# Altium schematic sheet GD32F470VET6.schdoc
size 127 x 101 mm
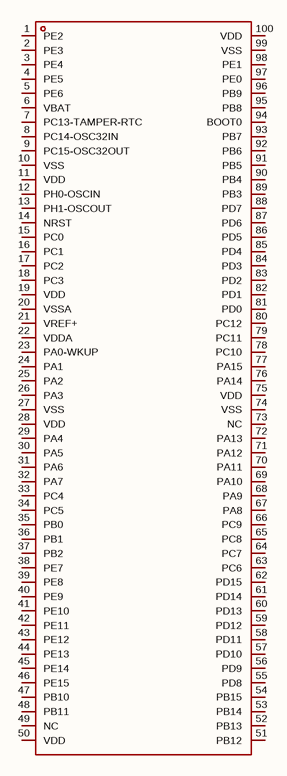
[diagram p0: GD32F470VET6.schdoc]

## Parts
U?  gd32f470vet6  [LQFP-100_L14.0-W14.0-P0.50-LS16.0-BL]  (value not drawn)

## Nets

Not connected (* = marked no-connect by the designer): U? 1(PE2) 2(PE3) 3(PE4) 4(PE5) 5(PE6) 6(VBAT) 7(PC13-TAMPER-RTC) 8(PC14-OSC32IN) 9(PC15-OSC32OUT) 10(VSS) 11(VDD) 12(PH0-OSCIN) 13(PH1-OSCOUT) 14(NRST) 15(PC0) 16(PC1) 17(PC2) 18(PC3) 19(VDD) 20(VSSA) 21(VREF+) 22(VDDA) 23(PA0-WKUP) 24(PA1) 25(PA2) 26(PA3) 27(VSS) 28(VDD) 29(PA4) 30(PA5) 31(PA6) 32(PA7) 33(PC4) 34(PC5) 35(PB0) 36(PB1) 37(PB2) 38(PE7) 39(PE8) 40(PE9) 41(PE10) 42(PE11) 43(PE12) 44(PE13) 45(PE14) 46(PE15) 47(PB10) 48(PB11) 49(NC) 50(VDD) 51(PB12) 52(PB13) 53(PB14) 54(PB15) 55(PD8) 56(PD9) 57(PD10) 58(PD11) 59(PD12) 60(PD13) 61(PD14) 62(PD15) 63(PC6) 64(PC7) 65(PC8) 66(PC9) 67(PA8) 68(PA9) 69(PA10) 70(PA11) 71(PA12) 72(PA13) 73(NC) 74(VSS) 75(VDD) 76(PA14) 77(PA15) 78(PC10) 79(PC11) 80(PC12) 81(PD0) 82(PD1) 83(PD2) 84(PD3) 85(PD4) 86(PD5) 87(PD6) 88(PD7) 89(PB3) 90(PB4) 91(PB5) 92(PB6) 93(PB7) 94(BOOT0) 95(PB8) 96(PB9) 97(PE0) 98(PE1) 99(VSS) 100(VDD)

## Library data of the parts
U? = gd32f470vet6: CPU内核:ARM Cortex-M系列;CPU最大主频:240MHz;; Manufacturer: GigaDevice(兆易创新); AddInBom: yes; ModelId: 469e6cc70557486dbd01fd12ff814964; ModelName: LQFP-100_L14.0-W14.0-H1.4-LS16.0-P0.50; ModelTransform: 629.92,629.92,0,0,0,0,0,0,0; CPU Maximum Speed: 240MHz; Program Storage Size: 512KB; Program Memory Type: FLASH; Number of I/O: 140; ADC (Bit): 10bit；8bit；6bit；12bit; DAC (Bit): 12bit; Voltage - Supply: 2.6V~3.6V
